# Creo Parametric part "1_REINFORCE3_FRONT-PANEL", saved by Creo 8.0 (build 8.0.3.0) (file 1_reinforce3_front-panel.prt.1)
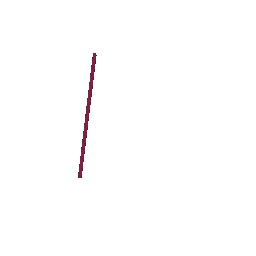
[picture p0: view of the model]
Units: millimeter Newton Second (mmNs); MM, TONNE, SECS

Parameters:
  SMT_DFLT_BEND_REL_LENGTH_TYPE = "Through All"

Other parameters: SMT_THICKNESS, SMT_PART_BEND_ALLOWANCE_FACTOR, SMT_DFLT_BEND_RADIUS, SMT_DFLT_BEND_ANGLE, SMT_DFLT_CRNR_REL_WIDTH, SMT_DFLT_CRNR_REL_DEPTH, SMT_DFLT_BEND_REL_WIDTH, SMT_DFLT_BEND_REL_DEPTH, SMT_DFLT_BEND_REL_LENGTH, SMT_DFLT_BEND_REL_ANGLE, SMT_GAP, SMT_DFLT_EDGE_TREA_WIDTH, SMT_DFLT_MITER_CUT_WIDTH, SMT_DFLT_MITER_CUT_OFFSET

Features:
  1. datum plane "DTM1"
  2. datum plane "DTM2"
  3. datum plane "DTM3"
  4. coordinate system
  5. protrusion
  6. round
  7. cut

Other named items: CS0

Layers: 0_ALL_AXIS, 0_ALL_CSYS, 0_ALL_CURVES, 0_ALL_PLANES, 0_ALL_POINTS, 0_ALL_SURFS, REINFORCE3_FRONT-PANEL

Surfaces: 24 plane, 15 cylinder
